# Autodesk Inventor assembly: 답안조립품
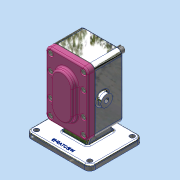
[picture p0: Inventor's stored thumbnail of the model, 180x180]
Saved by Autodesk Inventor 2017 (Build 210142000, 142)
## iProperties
Part Number: 답안조립품
Material: 일반
Document SubType Name: Assembly
Designer: MRC
Author: MRC
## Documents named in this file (11)
- C:\Users\MRC\Desktop\700407V1042\답안조립품.iam
- C:\Users\MRC\Desktop\700407V1042\본체.ipt
- C:\Users\MRC\Desktop\700407V1042\개스킷.ipt
- C:\Users\MRC\Desktop\700407V1042\메인축.ipt
- C:\Users\MRC\Desktop\700407V1042\베어링부시.ipt
- C:\Users\MRC\Desktop\700407V1042\볼트 M5.ipt
- C:\Users\MRC\Desktop\700407V1042\서브축.ipt
- C:\Users\MRC\Desktop\700407V1042\스퍼기어.ipt
- C:\Users\MRC\Desktop\700407V1042\오일 실 16 28 7.ipt
- C:\Users\MRC\Desktop\700407V1042\커버.ipt
- C:\Users\MRC\Desktop\700407V1042\키 6 x 6 x 18.ipt
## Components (1 placed, 1 different names)
1. 개스킷:1
